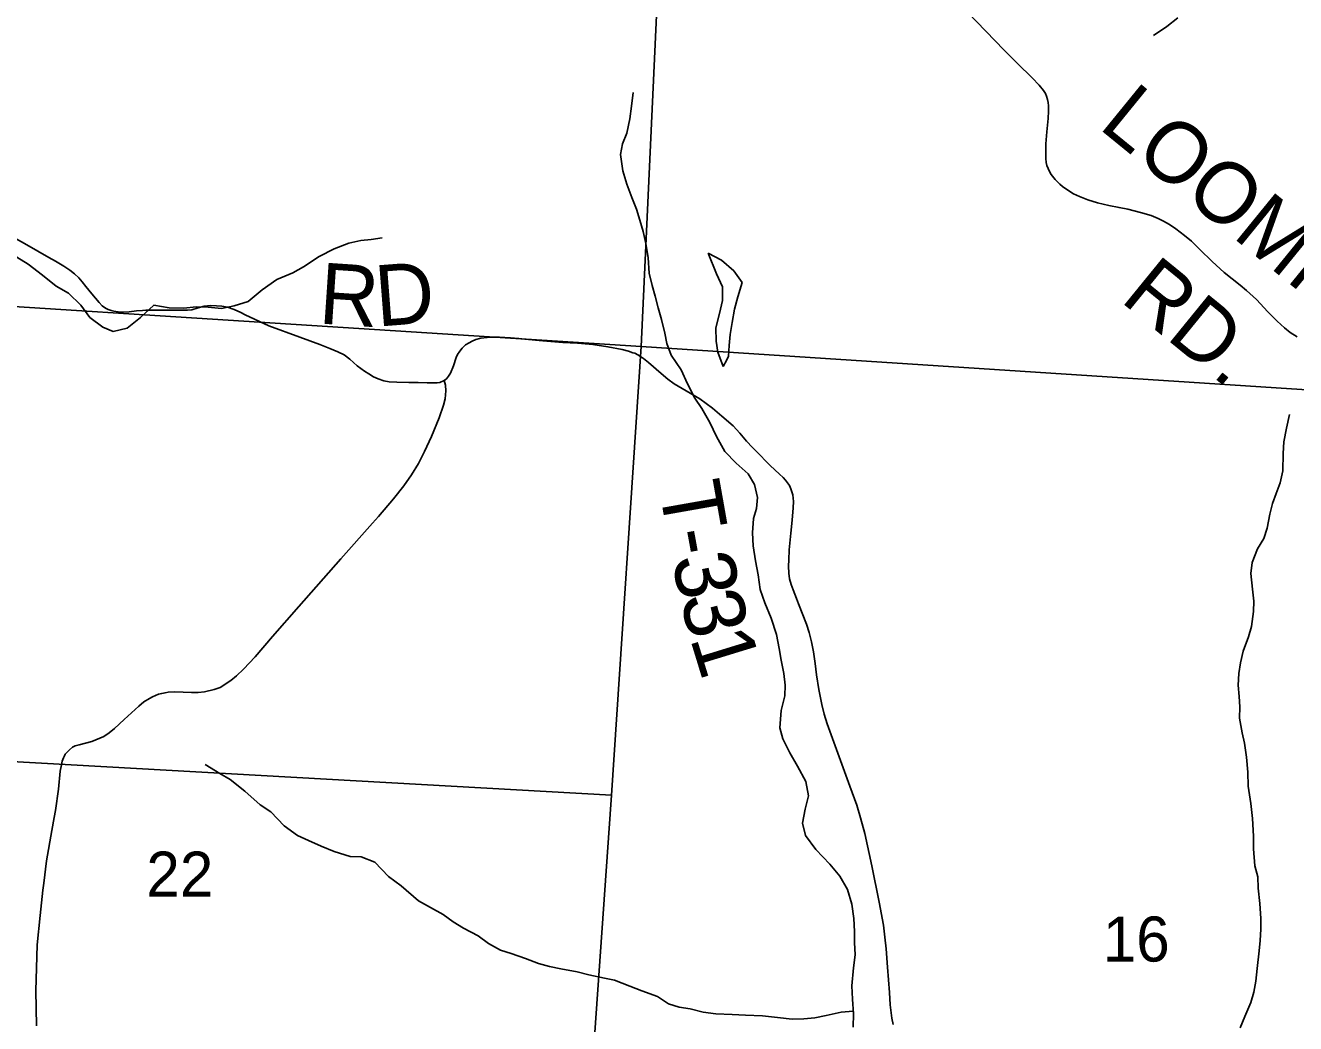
# Model space of a CAD drawing. Extents: x 0 to 34, y 0 to 22.
# Drawn here: x 5.819 to 6.999, y 16.091 to 17.019 of the extents above; entities that cross this region are included whole.
import ezdxf

# ---------------------------------------------------------------- set-up
doc = ezdxf.new("R2010")
doc.units = 0
for name, color, linetype in [('GM_X_Corporation', 7, 'Continuous'), ('GM_X_Minor_Lake', 7, 'Continuous'), ('GM_X_Minor_River', 7, 'Continuous'), ('GM_X_Section_Text', 7, 'Continuous'), ('GM_X_Township_Road', 7, 'Continuous'), ('GM_X_Township_Road_Text', 7, 'Continuous')]:
    doc.layers.add(name, color=color, linetype=linetype)

msp = doc.modelspace()

# ---------------------------------------------------------------- linework, layer by layer
at = {"layer": 'GM_X_Corporation'}
for points in [[(6.4386, 17.7441), (6.3912, 16.7203), (5.3901, 16.7843), (5.4592, 17.8072)], [(6.4386, 17.7441), (7.4643, 17.6703), (7.3858, 16.6558), (6.3912, 16.7203)], [(6.3912, 16.7203), (6.3636, 16.3035), (5.359, 16.3599), (5.3901, 16.7843)], [(6.3912, 16.7203), (7.3858, 16.6558), (7.3548, 16.2394), (7.3238, 15.8259), (7.3098, 15.6422), (6.7101, 15.6799), (6.3225, 15.705), (6.3352, 15.898), (6.3636, 16.3035)], [(6.3636, 16.3035), (6.3352, 15.898), (5.3297, 15.9601), (5.359, 16.3599)]]:
    msp.add_lwpolyline(points, close=True, dxfattribs=at)
at = {"layer": 'GM_X_Minor_Lake'}
for p, q in [((6.4533, 16.8072), (6.4611, 16.7879)), ((6.4659, 16.8008), (6.4533, 16.8072)), ((6.4773, 16.7907), (6.4659, 16.8008)), ((6.4611, 16.7879), (6.4669, 16.7758)), ((6.485, 16.7798), (6.4773, 16.7907)), ((6.4669, 16.7758), (6.4666, 16.7633)), ((6.4809, 16.7665), (6.485, 16.7798)), ((6.4666, 16.7633), (6.464, 16.7512)), ((6.478, 16.7551), (6.4809, 16.7665)), ((6.464, 16.7512), (6.4607, 16.7379)), ((6.4758, 16.7426), (6.478, 16.7551)), ((6.474, 16.7316), (6.4758, 16.7426)), ((6.4607, 16.7379), (6.4609, 16.7254)), ((6.473, 16.7213), (6.474, 16.7316)), ((6.4609, 16.7254), (6.4625, 16.7152)), ((6.4625, 16.7152), (6.4675, 16.7019)), ((6.4723, 16.7115), (6.473, 16.7213)), ((6.4675, 16.7019), (6.4707, 16.7082)), ((6.4707, 16.7082), (6.4723, 16.7115))]:
    msp.add_line(p, q, dxfattribs=at)
at = {"layer": 'GM_X_Minor_River'}
for p, q in [((6.89, 17.026), (6.8798, 17.0179)), ((6.8798, 17.0179), (6.8674, 17.0095)), ((6.1403, 16.8198), (6.1505, 16.8215)), ((6.092, 16.8042), (6.106, 16.8112)), ((6.106, 16.8112), (6.1195, 16.8166)), ((6.1195, 16.8166), (6.1305, 16.819)), ((6.1305, 16.819), (6.1403, 16.8198)), ((5.8109, 16.8036), (5.8216, 16.7969)), ((6.0774, 16.7946), (6.092, 16.8042)), ((5.8216, 16.7969), (5.8349, 16.7867)), ((5.8349, 16.7867), (5.8475, 16.7766)), ((6.0525, 16.7827), (6.0676, 16.7889)), ((6.0676, 16.7889), (6.0774, 16.7946)), ((5.8475, 16.7766), (5.8589, 16.7699)), ((6.0389, 16.7731), (6.0525, 16.7827)), ((5.8589, 16.7699), (5.8703, 16.759)), ((6.013, 16.7581), (6.0258, 16.7623)), ((6.0258, 16.7623), (6.0389, 16.7731)), ((5.8703, 16.759), (5.8787, 16.7474)), ((5.926, 16.7474), (5.9384, 16.7589)), ((5.9384, 16.7589), (5.9524, 16.7564)), ((5.9524, 16.7564), (5.9657, 16.7561)), ((5.9657, 16.7561), (5.9778, 16.7574)), ((5.9778, 16.7574), (5.9888, 16.7571)), ((5.9888, 16.7571), (6.0013, 16.7557)), ((6.0013, 16.7557), (6.013, 16.7581)), ((5.8787, 16.7474), (5.8909, 16.7384)), ((5.9136, 16.7374), (5.926, 16.7474)), ((5.8909, 16.7384), (5.9004, 16.7343)), ((5.9004, 16.7343), (5.9136, 16.7374)), ((6.9909, 16.6446), (6.9938, 16.6571)), ((6.9884, 16.6317), (6.9909, 16.6446)), ((6.9875, 16.6048), (6.9877, 16.621)), ((6.9877, 16.621), (6.9884, 16.6317)), ((6.9849, 16.5937), (6.9875, 16.6048)), ((6.9812, 16.5839), (6.9849, 16.5937)), ((6.9753, 16.5645), (6.9779, 16.5744)), ((6.9779, 16.5744), (6.9812, 16.5839)), ((6.9728, 16.5516), (6.9753, 16.5645)), ((6.9698, 16.5421), (6.9728, 16.5516)), ((6.9639, 16.5325), (6.9698, 16.5421)), ((6.9591, 16.5196), (6.9639, 16.5325)), ((6.9576, 16.5094), (6.9591, 16.5196)), ((6.9593, 16.495), (6.9576, 16.5094)), ((6.9605, 16.4836), (6.9593, 16.495)), ((6.9602, 16.4742), (6.9605, 16.4836)), ((6.9584, 16.4601), (6.9602, 16.4742)), ((6.9555, 16.4506), (6.9584, 16.4601)), ((6.9507, 16.4373), (6.9555, 16.4506)), ((6.9481, 16.4263), (6.9507, 16.4373)), ((6.9467, 16.4164), (6.9481, 16.4263)), ((6.946, 16.4058), (6.9467, 16.4164)), ((6.9469, 16.3952), (6.946, 16.4058)), ((6.9474, 16.3854), (6.9469, 16.3952)), ((6.9471, 16.3751), (6.9474, 16.3854)), ((6.9498, 16.3615), (6.9471, 16.3751)), ((6.9518, 16.3517), (6.9498, 16.3615)), ((6.9538, 16.3388), (6.9518, 16.3517)), ((6.9551, 16.3248), (6.9538, 16.3388)), ((5.9997, 16.3237), (5.986, 16.3319)), ((6.0092, 16.3181), (5.9997, 16.3237)), ((6.0229, 16.3072), (6.0092, 16.3181)), ((6.9552, 16.3119), (6.9551, 16.3248)), ((6.0371, 16.2945), (6.0229, 16.3072)), ((6.9576, 16.2957), (6.9552, 16.3119)), ((6.0469, 16.2881), (6.0371, 16.2945)), ((6.9592, 16.2816), (6.9576, 16.2957)), ((6.0595, 16.275), (6.0469, 16.2881)), ((6.9601, 16.2654), (6.9592, 16.2816)), ((6.0717, 16.266), (6.0595, 16.275)), ((6.082, 16.2612), (6.0717, 16.266)), ((6.0938, 16.256), (6.082, 16.2612)), ((6.1059, 16.2511), (6.0938, 16.256)), ((6.9602, 16.2536), (6.9601, 16.2654)), ((6.1207, 16.2463), (6.1059, 16.2511)), ((6.1309, 16.2461), (6.1207, 16.2463)), ((6.1438, 16.2413), (6.1309, 16.2461)), ((6.9615, 16.2377), (6.9602, 16.2536)), ((6.1564, 16.2277), (6.1438, 16.2413)), ((6.9642, 16.2275), (6.9615, 16.2377)), ((6.1682, 16.2191), (6.1564, 16.2277)), ((6.1843, 16.2052), (6.1682, 16.2191)), ((6.9647, 16.2169), (6.9642, 16.2275)), ((6.966, 16.2029), (6.9647, 16.2169)), ((6.1953, 16.1989), (6.1843, 16.2052)), ((6.2071, 16.1926), (6.1953, 16.1989)), ((6.9669, 16.1889), (6.966, 16.2029)), ((6.2166, 16.1858), (6.2071, 16.1926)), ((6.2261, 16.1799), (6.2166, 16.1858)), ((6.9669, 16.179), (6.9669, 16.1889)), ((6.2398, 16.1728), (6.2261, 16.1799)), ((6.2493, 16.1657), (6.2398, 16.1728)), ((6.9663, 16.1684), (6.9669, 16.179)), ((6.2603, 16.1593), (6.2493, 16.1657)), ((6.9656, 16.1589), (6.9663, 16.1684)), ((6.2702, 16.1564), (6.2603, 16.1593)), ((6.2838, 16.1516), (6.2702, 16.1564)), ((6.2956, 16.1471), (6.2838, 16.1516)), ((6.9635, 16.1422), (6.9656, 16.1589)), ((6.3059, 16.1442), (6.2956, 16.1471)), ((6.3165, 16.142), (6.3059, 16.1442)), ((6.3316, 16.1391), (6.3165, 16.142)), ((6.3426, 16.1366), (6.3316, 16.1391)), ((6.357, 16.1333), (6.3426, 16.1366)), ((6.9624, 16.1305), (6.9635, 16.1422)), ((6.3665, 16.1315), (6.357, 16.1333)), ((6.3806, 16.1259), (6.3665, 16.1315)), ((6.3919, 16.1215), (6.3806, 16.1259)), ((6.9606, 16.1202), (6.9624, 16.1305)), ((6.4064, 16.1163), (6.3919, 16.1215)), ((6.4166, 16.1096), (6.4064, 16.1163)), ((6.9577, 16.1107), (6.9606, 16.1202)), ((6.4265, 16.1063), (6.4166, 16.1096)), ((6.4367, 16.1049), (6.4265, 16.1063)), ((6.4489, 16.1016), (6.4367, 16.1049)), ((6.4606, 16.1001), (6.4489, 16.1016)), ((6.5771, 16.1016), (6.5632, 16.0988)), ((6.5883, 16.1026), (6.5771, 16.1016)), ((6.9521, 16.0978), (6.9577, 16.1107)), ((6.4758, 16.0995), (6.4606, 16.1001)), ((6.4882, 16.0989), (6.4758, 16.0995)), ((6.5038, 16.0983), (6.4882, 16.0989)), ((6.5178, 16.0969), (6.5038, 16.0983)), ((6.5314, 16.0951), (6.5178, 16.0969)), ((6.5424, 16.0956), (6.5314, 16.0951)), ((6.5526, 16.0964), (6.5424, 16.0956)), ((6.5632, 16.0988), (6.5526, 16.0964)), ((6.9477, 16.0872), (6.9521, 16.0978))]:
    msp.add_line(p, q, dxfattribs=at)
msp.add_lwpolyline([(6.5882, 16.0877), (6.5885, 16.1002), (6.5876, 16.1138), (6.5868, 16.1263), (6.5885, 16.143), (6.5899, 16.1551), (6.5894, 16.1665), (6.5893, 16.1767), (6.5889, 16.1888), (6.5869, 16.2021), (6.583, 16.2157), (6.5757, 16.2281), (6.5665, 16.2394), (6.5535, 16.2529), (6.5439, 16.2661), (6.5412, 16.2775), (6.5437, 16.2904), (6.5466, 16.3029), (6.5442, 16.3161), (6.5366, 16.3305), (6.5293, 16.3429), (6.5227, 16.3557), (6.52, 16.3659), (6.5213, 16.3822), (6.5246, 16.3959), (6.5249, 16.4058), (6.5237, 16.4164), (6.5213, 16.4289), (6.5193, 16.4398), (6.517, 16.4527), (6.5119, 16.4678), (6.5061, 16.4821), (6.5018, 16.4946), (6.4998, 16.5082), (6.4974, 16.5211), (6.4954, 16.5351), (6.4946, 16.5472), (6.4956, 16.5605), (6.4982, 16.57), (6.4992, 16.5802), (6.4964, 16.5923), (6.4907, 16.6021), (6.4796, 16.6119), (6.4689, 16.6228), (6.4613, 16.6367), (6.4551, 16.6499), (6.4474, 16.6627), (6.4409, 16.6725), (6.4343, 16.6857), (6.4282, 16.6989), (6.419, 16.7125), (6.4151, 16.7231), (6.4131, 16.7329), (6.41, 16.7454), (6.4069, 16.7563), (6.4041, 16.7673), (6.4014, 16.7771), (6.3986, 16.7885), (6.3978, 16.8029), (6.3954, 16.8161), (6.393, 16.8274), (6.3899, 16.838), (6.3868, 16.8482), (6.3825, 16.8588), (6.3779, 16.8713), (6.374, 16.8837), (6.3719, 16.8989), (6.3738, 16.9087), (6.3778, 16.9186), (6.3807, 16.9319), (6.3822, 16.9437), (6.3836, 16.9566)], dxfattribs=at)
at = {"layer": 'GM_X_Township_Road'}
for points in [[(7.0007, 16.7294), (6.9943, 16.7335), (6.9889, 16.7378), (6.9822, 16.7439), (6.9735, 16.7528), (6.9629, 16.7641), (6.9538, 16.7724), (6.9478, 16.7776), (6.9331, 16.7893), (6.9219, 16.7993), (6.9102, 16.8105), (6.9025, 16.8183), (6.8961, 16.8237), (6.8881, 16.8299), (6.8822, 16.8338), (6.8766, 16.8369), (6.8716, 16.8395), (6.8652, 16.8421), (6.8553, 16.8449), (6.8433, 16.848), (6.8353, 16.8495), (6.8257, 16.8515), (6.8151, 16.8541), (6.8062, 16.8569), (6.7984, 16.8599), (6.793, 16.8623), (6.7877, 16.8656), (6.7826, 16.8692), (6.7802, 16.8712), (6.7759, 16.8757), (6.7721, 16.8804), (6.7706, 16.883), (6.7693, 16.8858), (6.7682, 16.8888), (6.7676, 16.8916), (6.7672, 16.8952), (6.7672, 16.8992), (6.7672, 16.9089), (6.7681, 16.9199), (6.7693, 16.9323), (6.7697, 16.9393), (6.7698, 16.944), (6.7695, 16.9473), (6.7689, 16.9501), (6.7679, 16.953), (6.7668, 16.9555), (6.7651, 16.9584), (6.7609, 16.9632), (6.7546, 16.97), (6.7409, 16.9836), (6.7304, 16.994), (6.7286, 16.9959), (6.6944, 17.0311)], [(5.8074, 16.8221), (5.8201, 16.8148), (5.8406, 16.8033), (5.847, 16.7999), (5.8545, 16.7952), (5.8602, 16.7913), (5.8644, 16.7881), (5.8686, 16.7842), (5.8717, 16.7807), (5.8752, 16.7763), (5.8808, 16.7694), (5.8876, 16.7612), (5.8904, 16.7583), (5.8933, 16.756), (5.8958, 16.7549), (5.8985, 16.754), (5.9011, 16.7533), (5.9051, 16.7528), (5.9095, 16.7525), (5.9154, 16.7528), (5.9222, 16.7536), (5.9277, 16.754), (5.9308, 16.7543), (5.9351, 16.7543), (5.9401, 16.7541), (5.949, 16.7542), (5.96, 16.7541), (5.9658, 16.7541), (5.9697, 16.7542), (5.9737, 16.7546), (5.9795, 16.7565), (5.9851, 16.7579), (5.991, 16.7584), (5.9965, 16.7583), (6.0015, 16.7578), (6.0066, 16.7569), (6.013, 16.7549), (6.0191, 16.7521), (6.023, 16.7499), (6.045, 16.7398), (6.0741, 16.7292), (6.0924, 16.7222), (6.1018, 16.7187), (6.1094, 16.7154), (6.1152, 16.7127), (6.1205, 16.7088), (6.1273, 16.7025), (6.1341, 16.6975), (6.1382, 16.695), (6.1423, 16.6924), (6.1467, 16.6903), (6.1521, 16.6886), (6.1571, 16.6876), (6.164, 16.6873), (6.1753, 16.687), (6.1838, 16.6869), (6.1924, 16.6867), (6.1971, 16.6866), (6.2017, 16.6867), (6.204, 16.6869), (6.208, 16.6887), (6.2103, 16.6905), (6.2121, 16.6928), (6.2141, 16.6958), (6.2168, 16.7024), (6.2192, 16.7102), (6.2206, 16.7129), (6.2227, 16.7161), (6.2247, 16.7188), (6.228, 16.7219), (6.2312, 16.724), (6.2342, 16.7255), (6.2375, 16.7268), (6.2422, 16.7281), (6.2479, 16.7288), (6.253, 16.729), (6.2594, 16.729), (6.2696, 16.7284), (6.2776, 16.7278), (6.2829, 16.7273), (6.2998, 16.7257), (6.3183, 16.7243), (6.3321, 16.7234), (6.3461, 16.7222), (6.3603, 16.7202), (6.3734, 16.7177), (6.3794, 16.7162), (6.3834, 16.7147), (6.3852, 16.7141), (6.388, 16.7127), (6.3906, 16.7112), (6.3932, 16.7094), (6.3979, 16.7055), (6.4097, 16.6952), (6.4159, 16.69), (6.4218, 16.6858), (6.4331, 16.6791), (6.4458, 16.6717), (6.4576, 16.6631), (6.4662, 16.6556), (6.4766, 16.6468), (6.4828, 16.64), (6.489, 16.6325), (6.4945, 16.6267), (6.4977, 16.6235), (6.5109, 16.6099), (6.5197, 16.6018), (6.5232, 16.5987), (6.5254, 16.5962), (6.5273, 16.5937), (6.5289, 16.5911), (6.5303, 16.5883), (6.5313, 16.5855), (6.532, 16.5825), (6.5325, 16.5795), (6.5326, 16.5765), (6.5324, 16.5704), (6.5314, 16.5591), (6.5301, 16.5468), (6.5287, 16.5314), (6.5283, 16.5221), (6.5282, 16.5163), (6.5283, 16.5099), (6.529, 16.5046), (6.5305, 16.4992), (6.5323, 16.4943), (6.5354, 16.4861), (6.5374, 16.4813), (6.5448, 16.4623), (6.5473, 16.4545), (6.5496, 16.4458), (6.5514, 16.4368), (6.5528, 16.4258), (6.5541, 16.4152), (6.5563, 16.4018), (6.5592, 16.3876), (6.5612, 16.3786), (6.5639, 16.3697), (6.5714, 16.3493), (6.5852, 16.3119), (6.5915, 16.2943), (6.5951, 16.2825), (6.5989, 16.2677), (6.6056, 16.2377), (6.6123, 16.204), (6.6164, 16.1826), (6.6177, 16.1715), (6.6189, 16.1606), (6.6202, 16.1437), (6.6219, 16.1201), (6.6225, 16.1085), (6.6242, 16.0962), (6.6255, 16.0902)], [(5.8292, 16.089), (5.8287, 16.1218), (5.8291, 16.1426), (5.83, 16.1642), (5.8327, 16.1917), (5.8351, 16.2151), (5.8361, 16.2217), (5.8385, 16.2423), (5.8436, 16.2705), (5.8457, 16.2827), (5.847, 16.2893), (5.8496, 16.309), (5.8513, 16.3257), (5.8524, 16.3315), (5.8532, 16.3351), (5.8542, 16.338), (5.8553, 16.34), (5.856, 16.3414), (5.8576, 16.3434), (5.8599, 16.3457), (5.8628, 16.348), (5.8653, 16.3493), (5.8688, 16.3503), (5.8807, 16.3534), (5.8918, 16.3581), (5.8969, 16.3615), (5.9017, 16.3653), (5.9108, 16.3737), (5.9243, 16.3862), (5.9291, 16.3901), (5.9343, 16.3934), (5.937, 16.3948), (5.9398, 16.3961), (5.9427, 16.3972), (5.9457, 16.398), (5.9487, 16.3987), (5.9517, 16.3991), (5.9579, 16.3994), (5.9733, 16.3988), (5.9794, 16.3988), (5.9855, 16.3995), (5.9944, 16.4015), (6, 16.4036), (6.0099, 16.4099), (6.015, 16.4142), (6.0217, 16.4207), (6.0323, 16.4321), (6.0486, 16.4508), (6.0731, 16.4789), (6.1121, 16.523), (6.1416, 16.5562), (6.1472, 16.5625), (6.1611, 16.5789), (6.1706, 16.591), (6.1776, 16.6012), (6.1841, 16.6118), (6.1899, 16.6228), (6.1963, 16.6369), (6.2033, 16.6542), (6.2074, 16.6659), (6.2089, 16.6719), (6.2097, 16.6793), (6.2092, 16.6844), (6.208, 16.6887)]]:
    msp.add_lwpolyline(points, dxfattribs=at)

# ---------------------------------------------------------------- texts
at = {"layer": 'GM_X_Section_Text'}
for s, p in [('22', (5.9313, 16.2091)), ('16', (6.8201, 16.1488))]:
    msp.add_text(s, height=0.04186, rotation=0, dxfattribs=at).set_placement(p)
at = {"layer": 'GM_X_Township_Road_Text'}
for s, height, rotation, p in [('LOOMIS', 0.05682, 320.8393, (6.8152, 16.924)), ('R', 0.0568, 356.1646, (6.0907, 16.7419)), ('D', 0.0568, 4.3993, (6.146, 16.7389)), ('RD.', 0.05682, 320.8393, (6.8353, 16.7631)), ('T', 0.0568, 280.0281, (6.4075, 16.59)), ('-', 0.0568, 280.3623, (6.415, 16.5478)), ('3', 0.0568, 281.5638, (6.4194, 16.5235)), ('3', 0.0568, 283.9053, (6.427, 16.4868)), ('1', 0.0568, 287.0564, (6.4363, 16.4495))]:
    msp.add_text(s, height=height, rotation=rotation, dxfattribs=at).set_placement(p)

doc.saveas('drawing.dxf')
